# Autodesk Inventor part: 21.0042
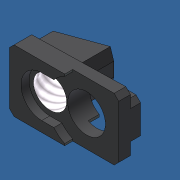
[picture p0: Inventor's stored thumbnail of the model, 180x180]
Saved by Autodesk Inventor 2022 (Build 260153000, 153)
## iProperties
Created: 2015-06
Part Number: 21.0042
Material: Stainless Steel
Document SubType Name: Modeling
Designer: Admin
Density: 8 g/cm^3
Mass: 8.11055 g
Surface Area: 12.7833 cm^2
Volume: 1.01382 cm^3
Appearance: Gray Speckled
Description: POWER-LOCK 30 BODY SS
Stock Number: 21.0042 POWER-LOCK 30 BODY SS
Author: Admin
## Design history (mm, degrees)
feature "Base1"
body "Solid1"
